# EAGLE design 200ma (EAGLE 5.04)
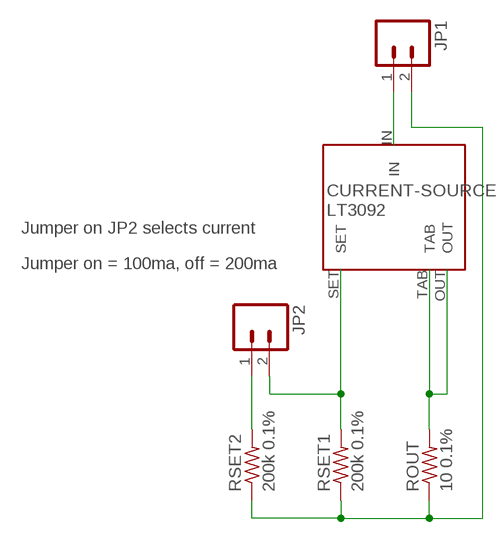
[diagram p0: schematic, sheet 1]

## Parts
CURRENT-SOURCE  LT3092  [SOT-223-3]
JP1  M02PTH  [1X02]
JP2  M02PTH  [1X02]
ROUT  10 0.1%  R-US_M1206  [M1206]
RSET1  200k 0.1%  R-US_M1206  [M1206]
RSET2  200k 0.1%  R-US_M1206  [M1206]

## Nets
N$1: CURRENT-SOURCE.OUT CURRENT-SOURCE.TAB ROUT.2
N$2: CURRENT-SOURCE.SET JP2.2 RSET1.2
N$3: JP1.2 ROUT.1 RSET1.1 RSET2.1
N$4: JP2.1 RSET2.2
N$6: CURRENT-SOURCE.IN JP1.1

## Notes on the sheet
- Jumper on JP2 selects current
- Jumper on = 100ma, off = 200ma

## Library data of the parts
CURRENT-SOURCE = trl:LT3092
JP1 JP2 = SparkFun:M02: Header 2
ROUT RSET1 RSET2 = resistor:R-US_: RESISTOR, American symbol

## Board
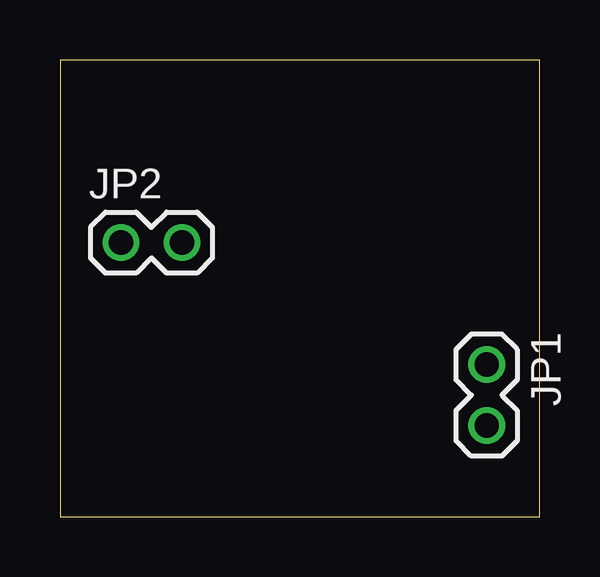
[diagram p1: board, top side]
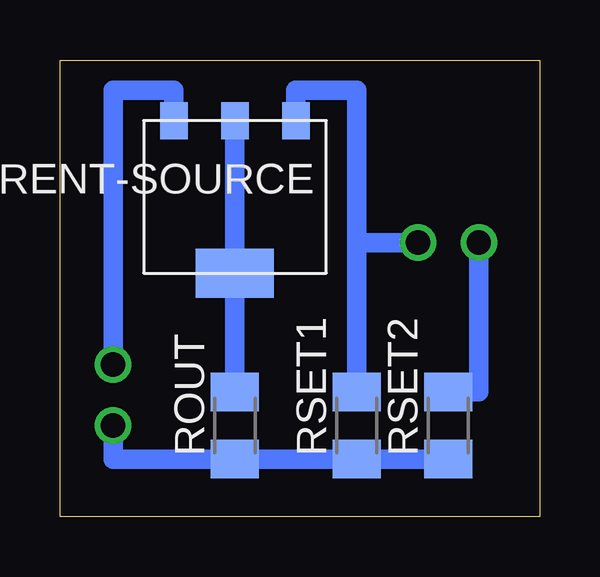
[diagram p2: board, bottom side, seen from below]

Size 19.99 x 19.04 mm. Coordinates in mm from the lower left corner, seen from the top.
Outline: 0,0 19.99,0 19.99,19.04 0,19.04 0,0
Copper layers (1*16): Top 0.035mm / dielectric 1.5mm / Bottom 0.035mm
Design rules "default": minimum track width 10mil, minimum drill 24mil, track to track 8mil, track to pad 8mil, pad to pad 8mil, via to via 8mil, smd to smd 8mil, copper to edge 40mil, drill to drill 8mil, minimum pad ring 10mil, minimum via ring 8mil, stop-mask expansion 4mil, vias tented up to drill 0mil, thermal gap 10mil

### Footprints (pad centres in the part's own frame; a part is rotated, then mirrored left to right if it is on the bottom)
SOT-223-3 = smd 1.143 x 1.524: IN 5.08,0; OUT 2.54,0; SET 0,0 | smd 3.251 x 2.032: TAB 2.54,6.35
1X02 = drill 1.016 round: 1 0,0; 2 2.54,0
M1206 = smd 1.6 x 2: 1 -1.4,0; 2 1.4,0

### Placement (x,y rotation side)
CURRENT-SOURCE  10.16,16.51 180 bottom
JP1  17.78,6.35 270 top
JP2  2.54,11.43 0 top
ROUT  12.7,3.81 90 bottom
RSET1  7.62,3.81 90 bottom
RSET2  3.81,3.81 90 bottom

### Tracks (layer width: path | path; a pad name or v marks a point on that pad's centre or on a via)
N$1
  Bottom 0.813: ROUT.2 CURRENT-SOURCE.TAB CURRENT-SOURCE.OUT
N$2
  Bottom 0.61: 7.62,11.43 7.62,17.78
  Bottom 0.813: RSET1.2 7.62,11.43 | 7.62,11.43 7.62,17.78 10.16,17.78 CURRENT-SOURCE.SET | 7.62,11.43 6.35,11.43 JP2.2
N$3
  Bottom 0.813: RSET2.1 RSET1.1 ROUT.1 17.78,2.41 JP1.2
N$4
  Bottom 0.813: RSET2.2 2.54,5.21 JP2.1
N$6
  Bottom 0.813: CURRENT-SOURCE.IN 15.24,17.78 17.78,17.78 JP1.1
